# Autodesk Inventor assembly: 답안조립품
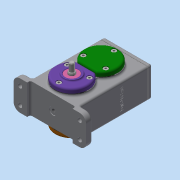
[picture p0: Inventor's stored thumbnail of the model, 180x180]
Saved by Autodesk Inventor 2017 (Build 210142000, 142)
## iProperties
Part Number: 답안조립품
Material: 일반
Document SubType Name: Assembly
Designer: mrc
Author: mrc
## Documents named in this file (24)
- C:\Users\mrc\Desktop\600506V1022\답안조립품.iam
- C:\Users\mrc\Desktop\600506V1022\본체.ipt
- C:\Users\mrc\Desktop\600506V1022\개스킷 A.ipt
- C:\Users\mrc\Desktop\600506V1022\개스킷 B.ipt
- C:\Users\mrc\Desktop\600506V1022\개스킷 C.ipt
- C:\Users\mrc\Desktop\600506V1022\베어링 6001.ipt
- 베어링 6001.ipt
- C:\Users\mrc\Desktop\600506V1022\베어링 6002.ipt
- 베어링 6002.ipt
- C:\Users\mrc\Desktop\600506V1022\볼트 M4.ipt
- C:\Users\mrc\Desktop\600506V1022\스퍼기어 A.ipt
- C:\Users\mrc\Desktop\600506V1022\스퍼기어 B.ipt
- C:\Users\mrc\Desktop\600506V1022\오일 실 10 20 7.ipt
- C:\Users\mrc\Desktop\600506V1022\오일 실 12 22 7.ipt
- C:\Users\mrc\Desktop\600506V1022\축 A.ipt
- C:\Users\mrc\Desktop\600506V1022\축 B.ipt
- C:\Users\mrc\Desktop\600506V1022\칼라.ipt
- C:\Users\mrc\Desktop\600506V1022\커버 A.ipt
- C:\Users\mrc\Desktop\600506V1022\커버 B.ipt
- C:\Users\mrc\Desktop\600506V1022\커버 C.ipt
- C:\Users\mrc\Desktop\600506V1022\커버 D.ipt
- C:\Users\mrc\Desktop\600506V1022\커버 E.ipt
- C:\Users\mrc\Desktop\600506V1022\키 4 x 4 x 12.ipt
- C:\Users\mrc\Desktop\600506V1022\키 5 x 5 x 12.ipt
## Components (5 placed, 3 different names)
1. 개스킷 A:1
2. 개스킷 B:1
3. 개스킷 C:1
4. 개스킷 B:2
5. 개스킷 B:3
